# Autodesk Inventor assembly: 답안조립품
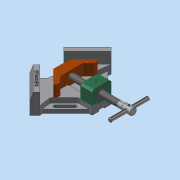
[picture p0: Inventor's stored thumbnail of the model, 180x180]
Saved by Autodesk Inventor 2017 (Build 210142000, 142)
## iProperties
Part Number: 답안조립품
Material: 일반
Document SubType Name: Assembly
Designer: 00-00
Author: 00-00
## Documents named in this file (11)
- C:\Users\00-00\Desktop\700506V1012\답안조립품.iam
- C:\Users\00-00\Desktop\700506V1012\베이스.ipt
- C:\Users\00-00\Desktop\700506V1012\리드스크류.ipt
- C:\Users\00-00\Desktop\700506V1012\멈춤나사 M4x5.ipt
- C:\Users\00-00\Desktop\700506V1012\멈춤나사 M4x10.ipt
- C:\Users\00-00\Desktop\700506V1012\볼트 M4x16.ipt
- C:\Users\00-00\Desktop\700506V1012\부시.ipt
- C:\Users\00-00\Desktop\700506V1012\서포트.ipt
- C:\Users\00-00\Desktop\700506V1012\조.ipt
- C:\Users\00-00\Desktop\700506V1012\평행 핀 2.5x24.ipt
- C:\Users\00-00\Desktop\700506V1012\핸들.ipt
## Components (1 placed, 1 different names)
1. 핸들:1
